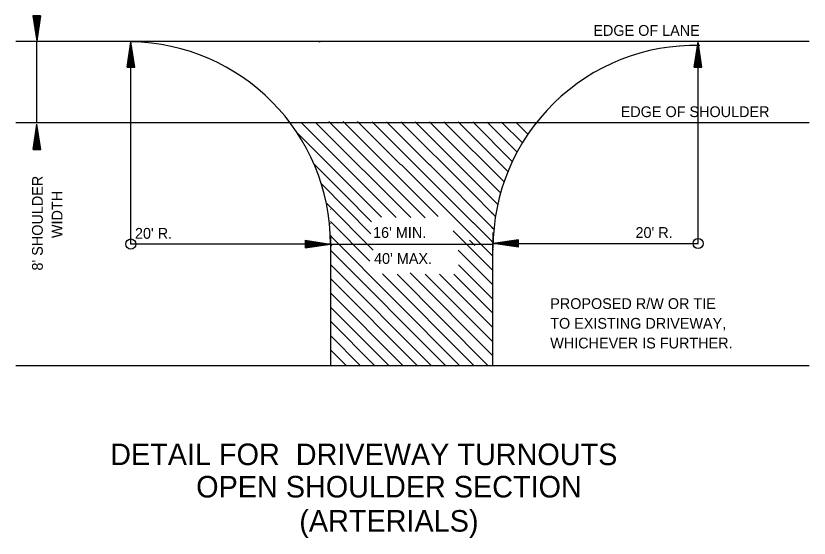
# Model space of a CAD drawing. Extents: x -2842 to 2681, y -2139 to 474.
# Drawn here: x -2436.5 to -1994.4, y -1082 to -791.2 of the extents above; entities that cross this region are included whole.
import ezdxf

# ---------------------------------------------------------------- set-up
doc = ezdxf.new("R2010")
doc.units = 0
doc.layers.add('Default', color=7, linetype='Continuous')

msp = doc.modelspace()

# ---------------------------------------------------------------- linework, layer by layer
at = {"layer": 'Default'}
for p, q in [((-2426.96, -791.18), (-2424.84, -805.33)), ((-2422.71, -791.18), (-2426.96, -791.18)), ((-2426.63, -791.18), (-2424.84, -802.97)), ((-2426.23, -791.18), (-2424.84, -800.54)), ((-2425.88, -791.18), (-2424.84, -798.18)), ((-2425.53, -791.18), (-2424.84, -795.77)), ((-2425.17, -791.18), (-2424.84, -793.47)), ((-2422.71, -791.18), (-2424.84, -805.33)), ((-2424.18, -791.18), (-2424.84, -795.77)), ((-2423.41, -791.18), (-2424.84, -800.54)), ((-2423.05, -791.18), (-2424.84, -802.97)), ((-2423.8, -791.18), (-2424.84, -798.18)), ((-2424.5, -791.18), (-2424.84, -793.47)), ((-2436.48, -805.33), (-1994.44, -805.33)), ((-2424.78, -850.51), (-2424.78, -805.33)), ((-2374.49, -819.81), (-2372.37, -805.68)), ((-2374.16, -819.81), (-2372.37, -808.07)), ((-2370.27, -819.81), (-2372.37, -805.68)), ((-2372.37, -918.21), (-2372.37, -805.68)), ((-2370.61, -819.81), (-2372.37, -808.07)), ((-2267.26, -805.8), (-2267.06, -805.18)), ((-2267.06, -805.38), (-2267.26, -805.8)), ((-2267.26, -805.8), (-2267.06, -805.6)), ((-2058.45, -819.75), (-2056.32, -805.6)), ((-2058.11, -819.75), (-2056.32, -808.01)), ((-2054.2, -819.75), (-2056.32, -805.6)), ((-2056.32, -917.91), (-2056.32, -805.6)), ((-2054.57, -819.75), (-2056.32, -808.01)), ((-2373.8, -819.81), (-2372.37, -810.49)), ((-2373.44, -819.81), (-2372.37, -812.82)), ((-2370.97, -819.81), (-2372.37, -810.49)), ((-2371.35, -819.81), (-2372.37, -812.82)), ((-2057.75, -819.75), (-2056.32, -810.42)), ((-2057.4, -819.75), (-2056.32, -812.76)), ((-2054.93, -819.75), (-2056.32, -810.42)), ((-2055.29, -819.75), (-2056.32, -812.76)), ((-2373.04, -819.81), (-2372.37, -815.23)), ((-2372.72, -819.81), (-2372.37, -817.58)), ((-2371.68, -819.81), (-2372.37, -815.23)), ((-2372.03, -819.81), (-2372.37, -817.58)), ((-2057.04, -819.75), (-2056.32, -815.18)), ((-2056.69, -819.75), (-2056.32, -817.52)), ((-2055.63, -819.75), (-2056.32, -815.18)), ((-2055.99, -819.75), (-2056.32, -817.52)), ((-2374.49, -819.81), (-2370.27, -819.81)), ((-2058.45, -819.75), (-2054.2, -819.75)), ((-2436.48, -850.51), (-1994.44, -850.51)), ((-2426.86, -865.55), (-2424.75, -851.41)), ((-2422.63, -865.55), (-2424.75, -851.41)), ((-2426.51, -865.55), (-2424.75, -853.82)), ((-2426.15, -865.55), (-2424.75, -856.22)), ((-2422.99, -865.55), (-2424.75, -853.82)), ((-2423.32, -865.55), (-2424.75, -856.22)), ((-2425.82, -865.55), (-2424.75, -858.57)), ((-2425.43, -865.55), (-2424.75, -860.98)), ((-2423.73, -865.55), (-2424.75, -858.57)), ((-2424.06, -865.55), (-2424.75, -860.98)), ((-2426.86, -865.55), (-2422.63, -865.55)), ((-2425.08, -865.55), (-2424.75, -863.33)), ((-2424.42, -865.55), (-2424.75, -863.33)), ((-2221.81, -873.85), (-2170.77, -925.05)), ((-2205.92, -873.94), (-2170.11, -909.86)), ((-2266.24, -884.78), (-2238.64, -912.48)), ((-2183.92, -888.09), (-2169.24, -902.81)), ((-2253.5, -890.53), (-2238.28, -905.8)), ((-2263.45, -895.5), (-2237.41, -921.62)), ((-2261.15, -905.73), (-2239.23, -927.73)), ((-2181.57, -906.29), (-2170.77, -917.13)), ((-2261.15, -913.23), (-2261.15, -918.51)), ((-2261.15, -913.65), (-2189.21, -985.81)), ((-2192.8, -910.89), (-2170.77, -932.98)), ((-2170.77, -911.71), (-2170.77, -918.15)), ((-2261.15, -918.21), (-2372.37, -918.21)), ((-2275.27, -916.12), (-2261.15, -918.21)), ((-2275.27, -916.12), (-2275.27, -920.36)), ((-2275.27, -916.44), (-2263.54, -918.21)), ((-2275.27, -916.81), (-2265.95, -918.21)), ((-2275.27, -917.22), (-2268.31, -918.21)), ((-2275.27, -917.53), (-2270.7, -918.21)), ((-2275.27, -917.89), (-2273.06, -918.21)), ((-2275.27, -920.36), (-2261.15, -918.21)), ((-2275.27, -918.93), (-2270.7, -918.21)), ((-2275.27, -919.64), (-2265.95, -918.21)), ((-2275.27, -920.03), (-2263.54, -918.21)), ((-2275.27, -919.28), (-2268.31, -918.21)), ((-2275.27, -918.57), (-2273.06, -918.21)), ((-2261.15, -918.21), (-2261.15, -985.81)), ((-2261.15, -918.21), (-2181.47, -918.21)), ((-2183.7, -918.21), (-2170.26, -918.21)), ((-2170.77, -985.93), (-2170.77, -917.91)), ((-2156.47, -915.79), (-2170.58, -917.91)), ((-2156.47, -920), (-2170.58, -917.91)), ((-2170.58, -917.91), (-2056.32, -917.91)), ((-2156.47, -916.12), (-2168.22, -917.91)), ((-2156.47, -919.67), (-2168.22, -917.91)), ((-2156.47, -916.48), (-2165.79, -917.91)), ((-2156.47, -919.31), (-2165.79, -917.91)), ((-2156.47, -916.84), (-2163.46, -917.91)), ((-2156.47, -918.93), (-2163.46, -917.91)), ((-2156.47, -917.17), (-2161.06, -917.91)), ((-2156.47, -918.57), (-2161.06, -917.91)), ((-2156.47, -917.58), (-2158.71, -917.91)), ((-2156.47, -918.25), (-2158.71, -917.91)), ((-2156.47, -920), (-2156.47, -915.79)), ((-2261.15, -921.58), (-2197.13, -985.81)), ((-2190.05, -921.58), (-2170.77, -940.9)), ((-2261.15, -929.52), (-2205.03, -985.81)), ((-2189.74, -929.8), (-2170.77, -948.83)), ((-2232.22, -934.77), (-2181.33, -985.81)), ((-2223.99, -935.08), (-2173.41, -985.81)), ((-2216.83, -934.33), (-2170.77, -980.53)), ((-2208.32, -934.96), (-2170.77, -972.62)), ((-2200.4, -934.98), (-2170.77, -964.68)), ((-2192.47, -934.99), (-2170.77, -956.75)), ((-2261.15, -937.44), (-2212.93, -985.81)), ((-2261.15, -945.37), (-2220.85, -985.81)), ((-2261.15, -953.31), (-2228.73, -985.81)), ((-2261.15, -961.23), (-2236.63, -985.81)), ((-2261.15, -969.16), (-2244.55, -985.81)), ((-2261.15, -977.08), (-2252.43, -985.81)), ((-2436.48, -985.81), (-1994.44, -985.81))]:
    msp.add_line(p, q, dxfattribs=at)
for points in [[(-2277.47, -850.51), (-2224.65, -903.37)], [(-2269.5, -850.51), (-2216.43, -903.53)], [(-2262.04, -849.98), (-2208.41, -903.61)], [(-2254.05, -850.01), (-2201.13, -902.89)], [(-2246.02, -850.04), (-2222.02, -874.06)], [(-2238.02, -850.1), (-2181.63, -906.35)], [(-2230.02, -850.1), (-2206.04, -874.06)], [(-2221.93, -850.12), (-2183.92, -888.09)], [(-2213.96, -850.15), (-2189.99, -874.06)], [(-2205.95, -850.18), (-2166.37, -889.73)], [(-2197.92, -850.24), (-2164.46, -883.67)], [(-2189.93, -850.24), (-2162.26, -877.8)], [(-2181.9, -850.24), (-2159.84, -872.27)], [(-2173.87, -850.27), (-2157.16, -866.99)], [(-2165.85, -850.28), (-2154.25, -861.88)], [(-2157.69, -850.51), (-2151.15, -857.06)], [(-2279.87, -856.1), (-2232.69, -903.32)], [(-2270.4, -873.56), (-2253.5, -890.53)], [(-2190.01, -874.06), (-2167.98, -896.16)], [(-2261.15, -898.79), (-2260.93, -899.01)], [(-2171.38, -900.66), (-2170.77, -901.28)], [(-2261.15, -906.77), (-2260.99, -907.01)], [(-2171.36, -908.76), (-2170.44, -909.65)], [(-2261.21, -914.71), (-2261.02, -914.93)], [(-2261.02, -918.59), (-2260.45, -919.17)], [(-2183.7, -916.01), (-2180.79, -918.95)], [(-2171.34, -916.75), (-2170.77, -917.29)], [(-2170.98, -920.77), (-2170.31, -921.41)]]:
    msp.add_lwpolyline(points, dxfattribs=at)
for centre in [(-2372.38, -918.22), (-2056.33, -917.9)]:
    msp.add_circle(centre, 2.82, dxfattribs=at)
for centre, radius, start, end in [((-2373.8, -918.36), 112.68, 0.0764, 89.2743), ((-2057.88, -920.35), 112.73, 88.7538, 180)]:
    msp.add_arc(centre, radius, start, end, dxfattribs=at)

# ---------------------------------------------------------------- texts
for s, height, p in [('EDGE OF LANE', 6, (-2114.68, -802.29)), ('EDGE OF SHOULDER', 6, (-2099.46, -847.53)), ("20' R.", 6, (-2370.12, -915.27)), ("16' MIN.", 6, (-2237.43, -914.8)), ("20' R.", 6, (-2091.2, -914.81)), ("40' MAX.", 6, (-2236.89, -929.28)), ('PROPOSED R/W OR TIE', 6, (-2138.72, -954.39)), ('TO EXISTING DRIVEWAY,', 6, (-2138.72, -965.37)), ('WHICHEVER IS FURTHER.', 6, (-2138.72, -976.34)), ('DETAIL FOR  DRIVEWAY TURNOUTS', 12, (-2383.92, -1041.31)), ('OPEN SHOULDER SECTION', 12, (-2336, -1059.33)), ('(ARTERIALS)', 12, (-2278.54, -1078.35))]:
    msp.add_text(s, height=height, dxfattribs=at).set_placement(p)
for s, p in [("8' SHOULDER", (-2421.48, -932.98)), ('WIDTH', (-2410.51, -914.91))]:
    msp.add_text(s, height=6, rotation=90, dxfattribs=at).set_placement(p)

doc.saveas('drawing.dxf')
